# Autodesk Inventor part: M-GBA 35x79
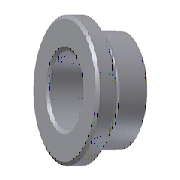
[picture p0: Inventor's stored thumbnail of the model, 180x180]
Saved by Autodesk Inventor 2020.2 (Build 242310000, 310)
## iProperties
Manager: www.cadconsulting.pl
Company: Fabian Stasiak CAD Consulting
Created: 2014-02
Part Number: M-GBA 35x79
Material: SUJ 2
Description: GUIDE BUSH
Document SubType Name: Modeling
Designer: F.Stasiak
Standard Revision: 1
Manufacturer: FUTABA
Language: pl-PL
Size Designation: 35x79
Categories: <MemberInstance><Categories><Category DisplayName="Forma wtryskowa" InternalName="349578f2-f4d4-4954-8c09-8e99297a61c0" Mnemonic="MOLD"><Category DisplayName="K
Density: 7.85 g/cm^3
Appearance: Domyślna
Catalog Web Link: www.expertbooks.pl
IsCustomPart: 0
Author: F.Stasiak
Subject: Zbiór ćwiczeń. Autodesk Inventor 2020. Kurs Professional
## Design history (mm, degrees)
sketch "Sketch1"
  geometry: L1 (0, -16.2)-(0, 6.2) reference; L2 (0, 10)-(27, 10); L3 (27, 10)-(27, 0); L4 (27, 0)-(23.5, 0); L5 (23.5, 0)-(23.5, -2); L6 (23.5, -2)-(24, -2); L7 (24, -2)-(24, -66); L8 (24, -66)-(23.75, -66); L9 (23.75, -66)-(23.75, -69); L10 (23.75, -69)-(0, -69); 1 further point
  constraints: 18 end point, 4 perpendicular, 2 parallel, 2 point on line, 1 horizontal alignment
  dimensions: "d0" = 79 distance between parallel lines of L10 L2 (= B); "d2" = 10 distance between parallel lines of L4 L2 (= T1); "d3" = 48 diameter of L7 L1 (= D); "d4" = 3 distance between parallel lines of L10 L8; "d5" = 47.5 diameter of L9 L1 (= D_Guide); "d6" = 54 diameter of L3 L1 (= D2); "d7" = 0.5 distance between parallel lines of L7 L5; "d8" = 2 distance between parallel lines of L4 L6
revolve "Revolution1" sketch "Sketch1" stored, may be unused: angle "d13" = 90 deg
sketch "Sketch2"
  geometry: L1 (-23.75, -69)-(23.75, -69) reference; L2 (0, -20.2)-(0, 30.2) reference; L3 (17.5, 10)-(17.5, -69); L4 (17.5, 10)-(17.75, 10); L5 (17.75, 10)-(17.75, 89); L6 (17.75, 89)-(0, 89); L7 (17.5, -69)-(0, -69); L8 (0, 89)-(0, -69)
  constraints: 12 end point, 3 perpendicular, 3 point on line, 1 collinear, 1 midpoint, 1 parallel
  dimensions: "d18" = 35 diameter of L3 L2 (= d_); "d20" = 79 distance between parallel lines of L1 L4 (= L1); "d21" = 79 distance between parallel lines of L4 L6 (= B); "d22" = 35.5 diameter of L5 L2 (= d1)
revolve "Revolution2" sketch "Sketch2" stored, may be unused: angle "d23" = 90 deg
chamfer "Chamfer1" distance "d24" = 0.5; stored, may be unused: second distance "d25" = 2, angle "d26" = 45 deg
fillet "Fillet1" dims "d27" = 0.3
fillet "Fillet2" dims "d28" = 0.8
body "Solid1"
other parameters: "d_" = 35 [user parameter; used in 1 equation term], "d1" = 35.5 [user parameter; used in 1 equation term], "L1" = 79 [user parameter; used in 1 equation term], "D" = 48 [user parameter; used in 1 equation term], "D2" = 54 [user parameter; used in 1 equation term], "B" = 79 [user parameter; used in 2 equation terms], "T1" = 10 [user parameter; used in 1 equation term], "D_Guide" = 47.5 [user parameter; used in 1 equation term], "d29" = 0, "d30" = 0, "d31" = 0
